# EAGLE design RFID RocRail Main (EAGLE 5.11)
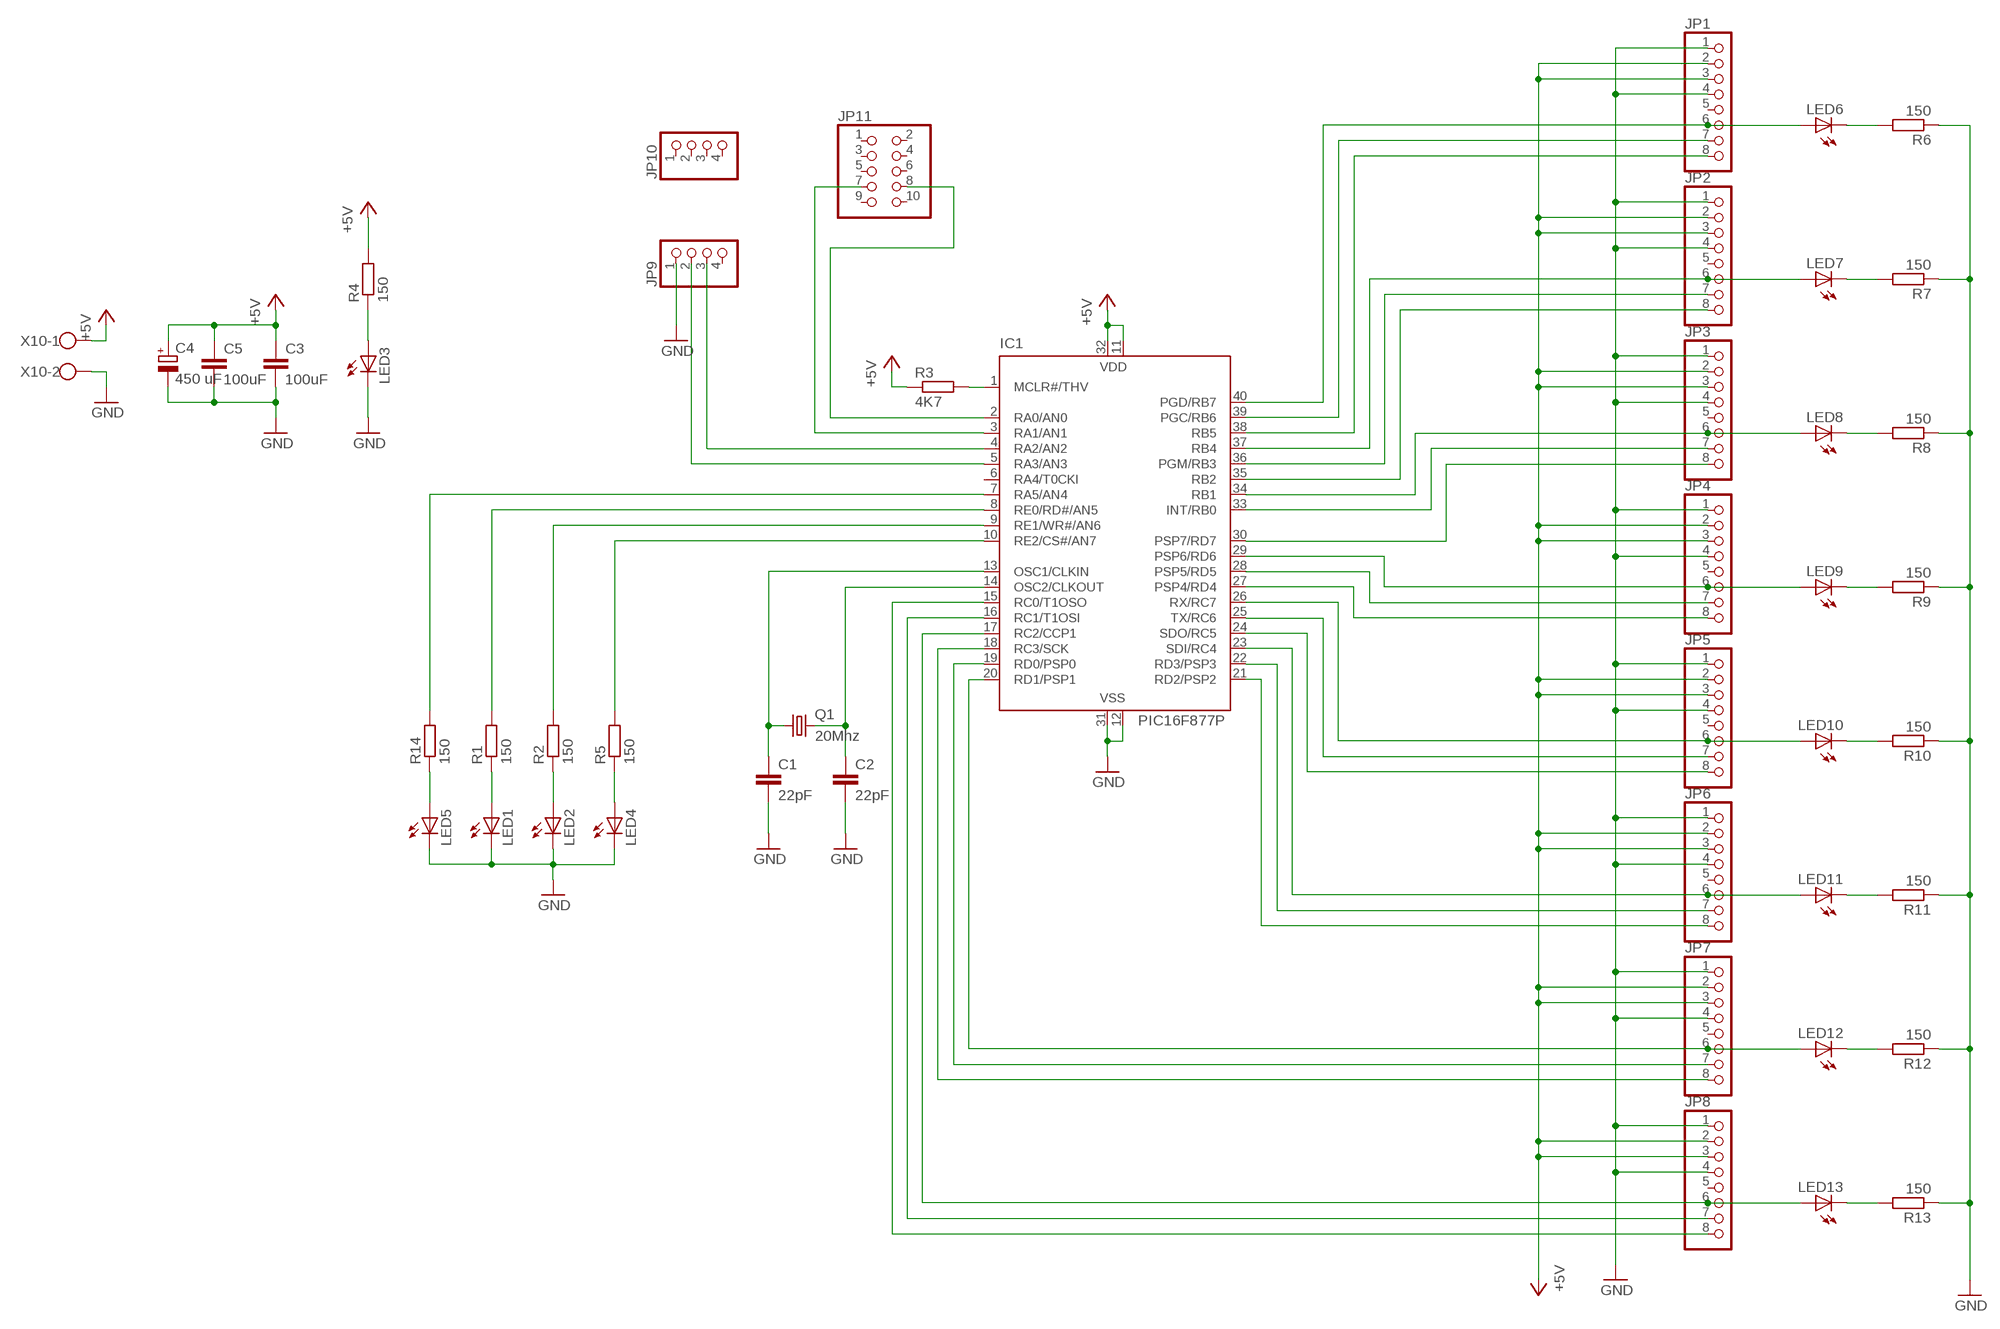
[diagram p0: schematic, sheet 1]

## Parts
C1  22pF  C-EU050-025X075  [C050-025X075]
C2  22pF  C-EU050-025X075  [C050-025X075]
C3  100uF  C-EU050-025X075  [C050-025X075]
C4  450 uF  CPOL-EUE5-13  [E5-13]
C5  100uF  C-EU050-025X075  [C050-025X075]
IC1  PIC16F877P  [DIL40]
JP1  PINHD-1X8  [1X08]
JP2  PINHD-1X8  [1X08]
JP3  PINHD-1X8  [1X08]
JP4  PINHD-1X8  [1X08]
JP5  PINHD-1X8  [1X08]
JP6  PINHD-1X8  [1X08]
JP7  PINHD-1X8  [1X08]
JP8  PINHD-1X8  [1X08]
JP9  PINHD-1X4  [1X04]
JP10  PINHD-1X4  [1X04]
JP11  PINHD-2X5  [2X05]
LED1  LED3MM  [LED3MM]
LED2  LED3MM  [LED3MM]
LED3  LED3MM  [LED3MM]
LED4  LED3MM  [LED3MM]
LED5  LED3MM  [LED3MM]
LED6  LED3MM  [LED3MM]
LED7  LED3MM  [LED3MM]
LED8  LED3MM  [LED3MM]
LED9  LED3MM  [LED3MM]
LED10  LED3MM  [LED3MM]
LED11  LED3MM  [LED3MM]
LED12  LED3MM  [LED3MM]
LED13  LED3MM  [LED3MM]
Q1  20Mhz  CRYSTALHC18U-V  [HC18U-V]
R1  150  R-EU_0207/2V  [0207/2V]
R2  150  R-EU_0207/2V  [0207/2V]
R3  4K7  R-EU_0204/7  [0204/7]
R4  150  R-EU_0204/7  [0204/7]
R5  150  R-EU_0207/2V  [0207/2V]
R6  150  R-EU_0204/7  [0204/7]
R7  150  R-EU_0204/7  [0204/7]
R8  150  R-EU_0204/7  [0204/7]
R9  150  R-EU_0204/7  [0204/7]
R10  150  R-EU_0204/7  [0204/7]
R11  150  R-EU_0204/7  [0204/7]
R12  150  R-EU_0204/7  [0204/7]
R13  150  R-EU_0204/7  [0204/7]
R14  150  R-EU_0207/2V  [0207/2V]
X10  W237-102  [W237-102]

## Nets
+5V: C3.1 C4.+ C5.1 IC1.11(VDD) IC1.32(VDD) JP1.2 JP1.3 JP2.2 JP2.3 JP3.2 JP3.3 JP4.2 JP4.3 JP5.2 JP5.3 JP6.2 JP6.3 JP7.2 JP7.3 JP8.2 JP8.3 R3.1 R4.2 X10.1
GND: C1.2 C2.2 C3.2 C4.- C5.2 IC1.12(VSS) IC1.31(VSS) JP1.1 JP1.4 JP2.1 JP2.4 JP3.1 JP3.4 JP4.1 JP4.4 JP5.1 JP5.4 JP6.1 JP6.4 JP7.1 JP7.4 JP8.1 JP8.4 JP9.1 LED1.K(C) LED2.K(C) LED3.K(C) LED4.K(C) LED5.K(C) R6.1 R7.1 R8.1 R9.1 R10.1 R11.1 R12.1 R13.1 X10.2
N$1: IC1.10(RE2/CS#/AN7) R5.2
N$2: IC1.9(RE1/WR#/AN6) R2.2
N$3: IC1.8(RE0/RD#/AN5) R1.2
N$4: IC1.15(RC0/T1OSO) JP8.8
N$5: IC1.16(RC1/T1OSI) JP8.7
N$6: IC1.17(RC2/CCP1) JP8.6 LED13.A
N$7: IC1.18(RC3/SCK) JP7.8
N$8: IC1.19(RD0/PSP0) JP7.7
N$9: C1.1 IC1.13(OSC1/CLKIN) Q1.1
N$10: IC1.20(RD1/PSP1) JP7.6 LED12.A
N$11: IC1.21(RD2/PSP2) JP6.8
N$12: IC1.22(RD3/PSP3) JP6.7
N$13: IC1.23(SDI/RC4) JP6.6 LED11.A
N$14: IC1.24(SDO/RC5) JP5.8
N$15: IC1.25(TX/RC6) JP5.7
N$16: IC1.26(RX/RC7) JP5.6 LED10.A
N$17: IC1.27(PSP4/RD4) JP4.8
N$18: IC1.28(PSP5/RD5) JP4.7
N$19: IC1.29(PSP6/RD6) JP4.6 LED9.A
N$20: IC1.30(PSP7/RD7) JP3.8
N$21: IC1.33(INT/RB0) JP3.7
N$22: IC1.34(RB1) JP3.6 LED8.A
N$23: IC1.35(RB2) JP2.8
N$24: IC1.36(PGM/RB3) JP2.7
N$25: IC1.37(RB4) JP2.6 LED7.A
N$26: IC1.38(RB5) JP1.8
N$27: IC1.39(PGC/RB6) JP1.7
N$28: IC1.40(PGD/RB7) JP1.6 LED6.A
N$29: IC1.4(RA2/AN2) JP9.3
N$30: C2.1 IC1.14(OSC2/CLKOUT) Q1.2
N$31: IC1.1(MCLR#/THV) R3.2
N$32: IC1.5(RA3/AN3) JP9.2
N$33: IC1.3(RA1/AN1) JP11.7
N$34: LED3.A R4.1
N$35: LED1.A R1.1
N$36: LED2.A R2.1
N$37: IC1.2(RA0/AN0) JP11.8
N$38: IC1.7(RA5/AN4) R14.2
N$39: LED5.A R14.1
N$40: LED6.K(C) R6.2
N$41: LED7.K(C) R7.2
N$42: LED8.K(C) R8.2
N$43: LED9.K(C) R9.2
N$44: LED10.K(C) R10.2
N$45: LED11.K(C) R11.2
N$46: LED12.K(C) R12.2
N$47: LED13.K(C) R13.2
N$72: LED4.A R5.1
Unconnected: IC1.6(RA4/T0CKI) JP1.5 JP2.5 JP3.5 JP4.5 JP5.5 JP6.5 JP7.5 JP8.5 JP9.4 JP10.1 JP10.2 JP10.3 JP10.4 JP11.1 JP11.2 JP11.3 JP11.4 JP11.5 JP11.6 JP11.9 JP11.10

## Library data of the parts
C1-C3 C5 = rcl:C-EU: CAPACITOR, European symbol
C4 = rcl:CPOL-EU: POLARIZED CAPACITOR, European symbol
IC1 = microchip:PIC16F87*: MICROCONTROLLER
JP1-JP8 = pinhead:PINHD-1X8: PIN HEADER
JP9 JP10 = pinhead:PINHD-1X4: PIN HEADER
JP11 = pinhead:PINHD-2X5: PIN HEADER
LED1-LED13 = led:LED: LED
Q1 = crystal:CRYSTAL: CRYSTAL
R1-R14 = rcl:R-EU_: RESISTOR, European symbol
X10 = con-wago-500:W237-102: WAGO SCREW CLAMP

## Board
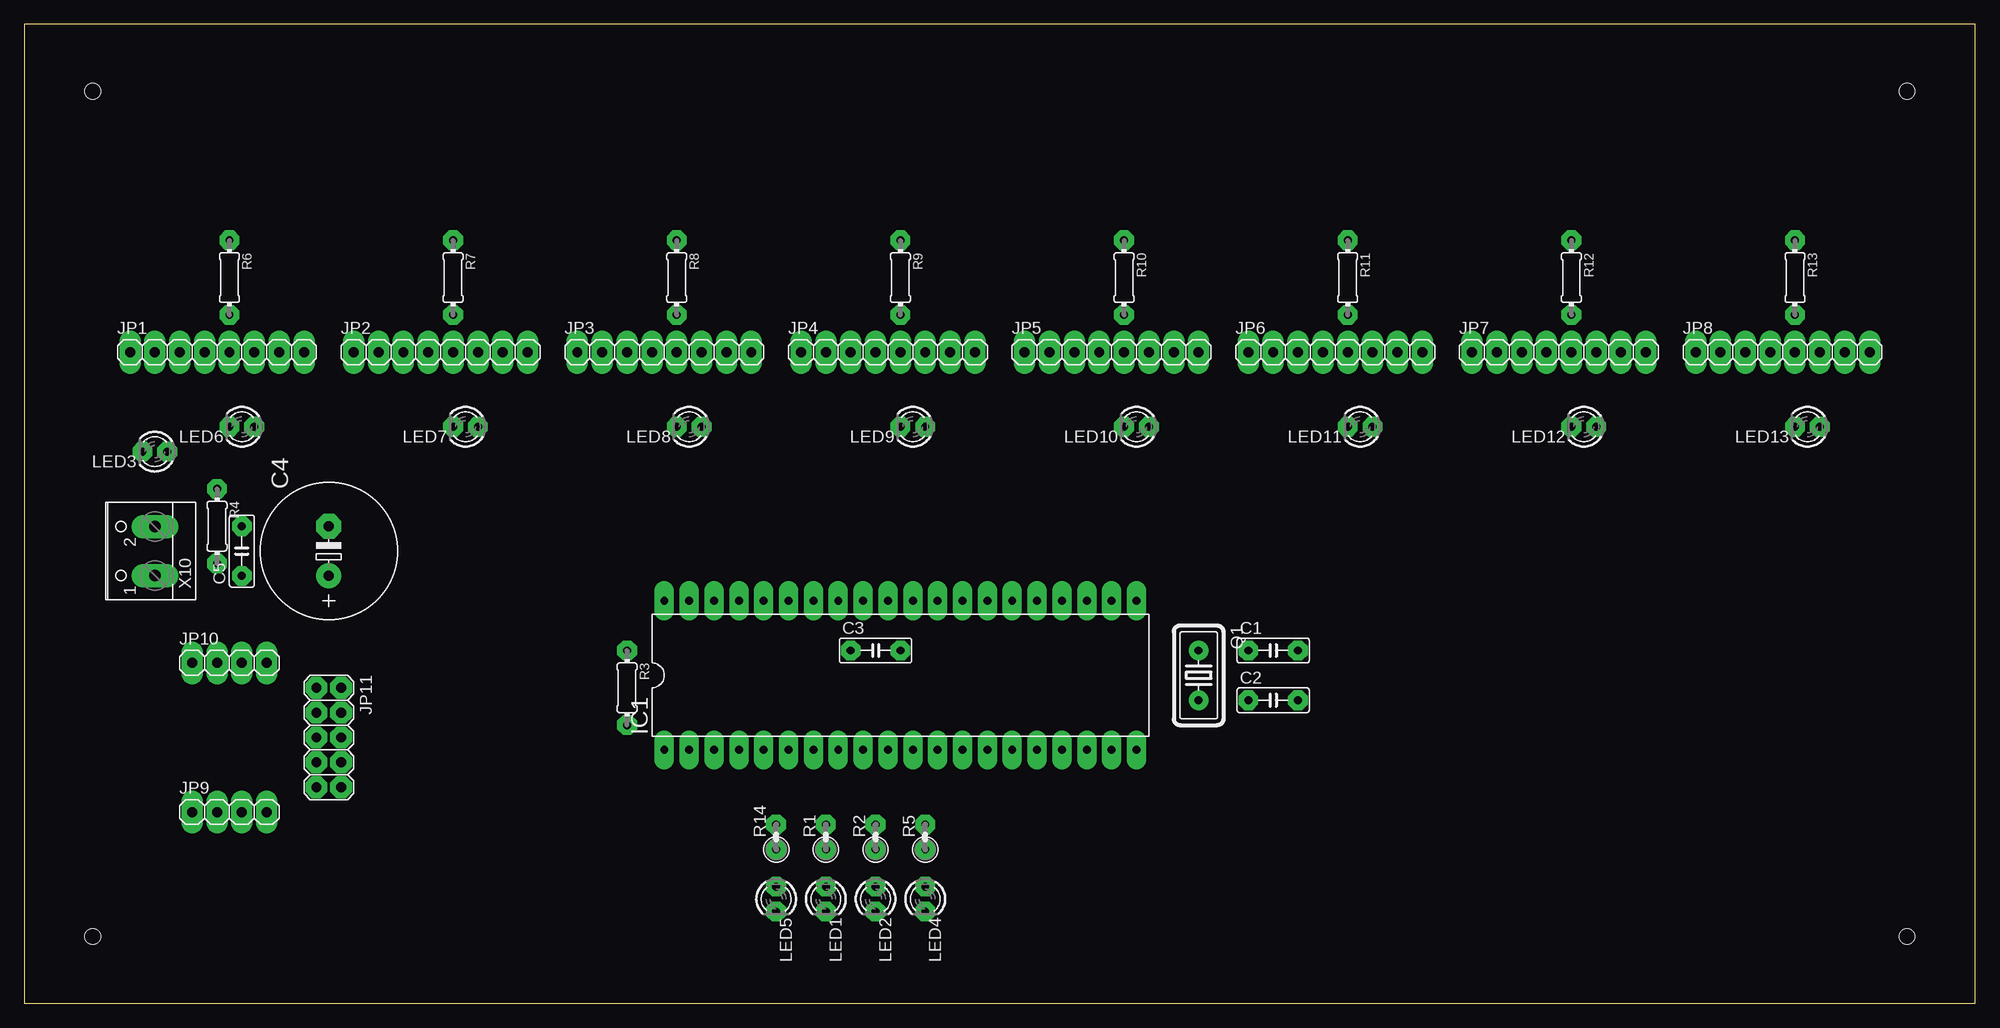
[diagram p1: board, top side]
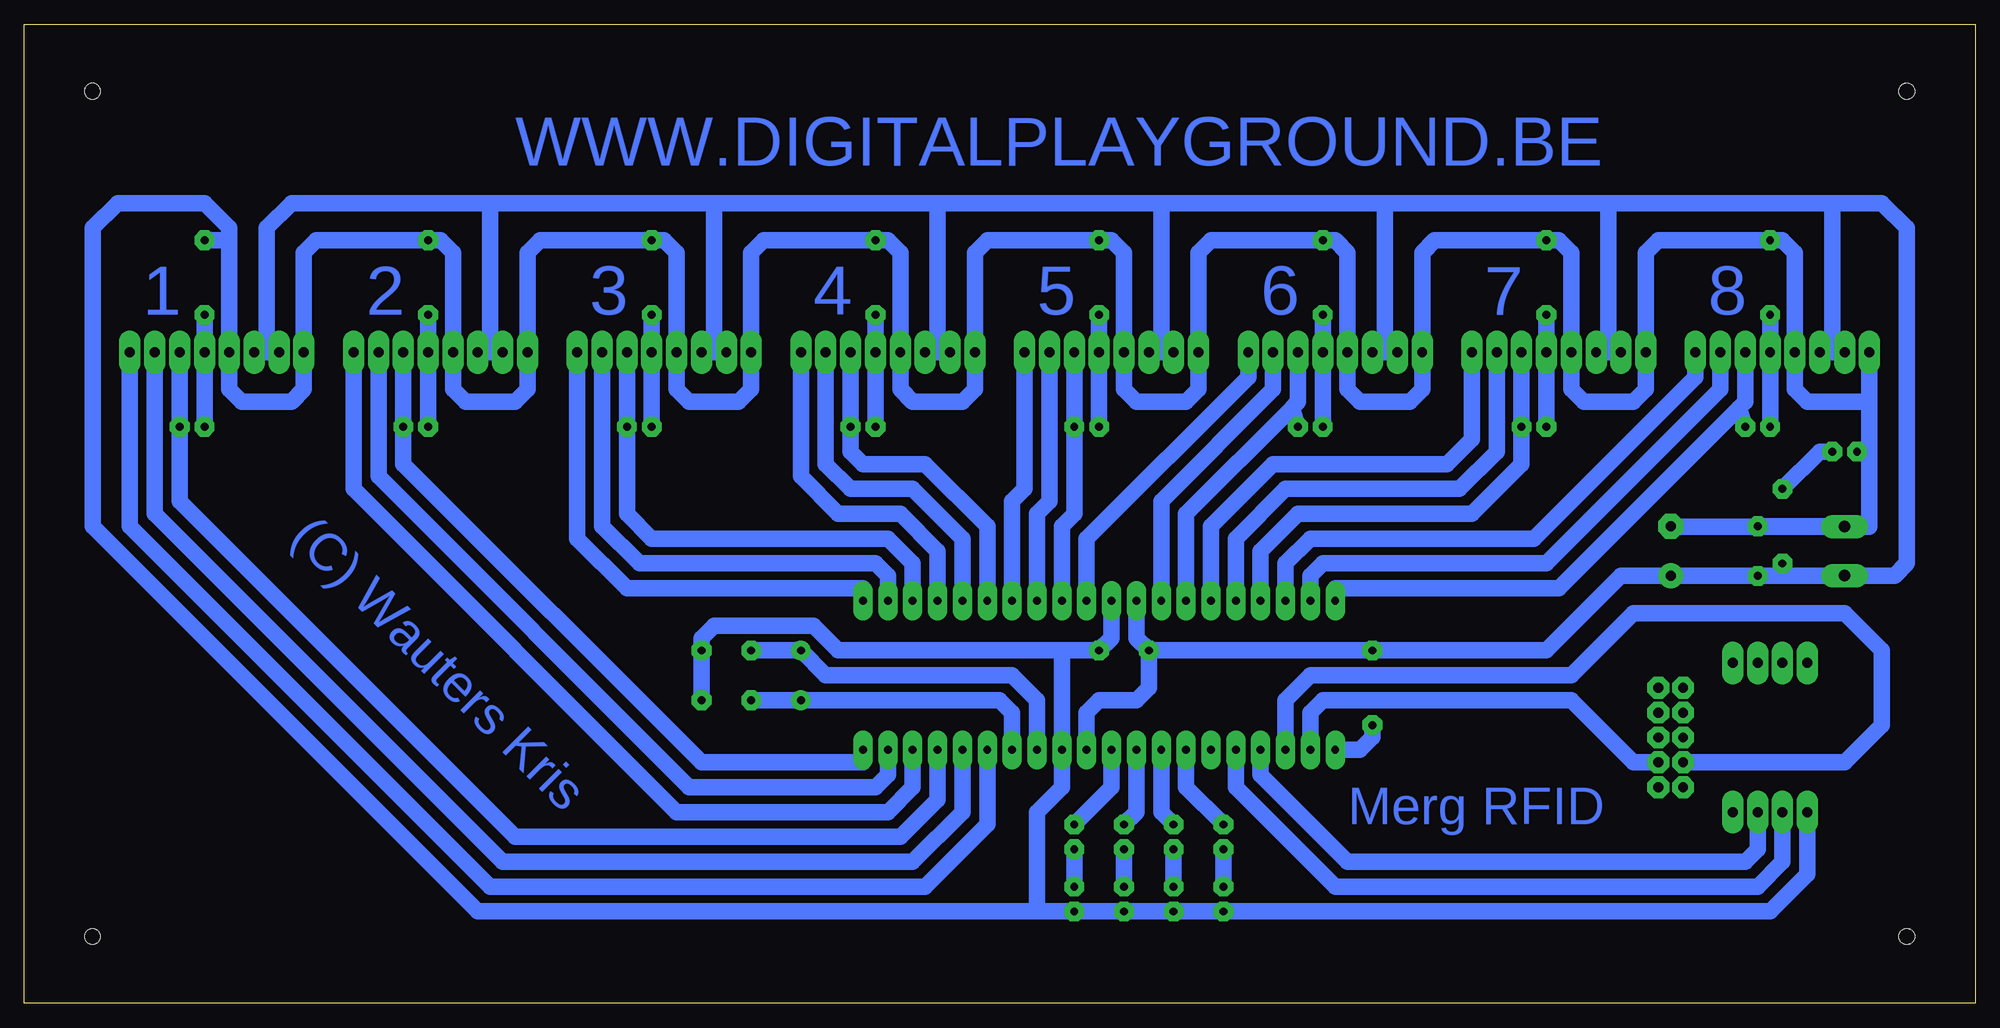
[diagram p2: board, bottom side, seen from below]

Size 199.37 x 100 mm. Coordinates in mm from the lower left corner, seen from the top.
Outline: 0,0 199.37,0 199.37,100 0,100 0,0
Copper layers (1*16): Top 1mm / dielectric 1.5mm / Bottom 1mm
Design rules "DRC settings middle": minimum track width 1.2mm, minimum drill 24mil, track to track 0.4mm, track to pad 0.4mm, pad to pad 0.4mm, via to via 0.4mm, smd to smd 8mil, copper to edge 0.5mm, drill to drill 0.5mm, minimum pad ring 0.6mm, minimum via ring 1mm, stop-mask expansion 4mil, vias tented up to drill 0mil, thermal gap 10mil
Holes 1.6 mm at 6.98,93.18 192.4,93.18 6.98,6.82 192.4,6.82

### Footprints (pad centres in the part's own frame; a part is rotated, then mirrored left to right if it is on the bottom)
C050-025X075 = drill 0.813 octagon: 1 -2.54,0; 2 2.54,0
E5-13 = drill 1.016 pad 2.54 round: + -2.54,0 | drill 1.016 pad 2.54 octagon: - 2.54,0
DIL40 = drill 0.813 long: 1 -24.13,-7.62; 2 -21.59,-7.62; 3 -19.05,-7.62; 4 -16.51,-7.62; 5 -13.97,-7.62; 6 -11.43,-7.62; 7 -8.89,-7.62; 8 -6.35,-7.62; 9 -3.81,-7.62; 10 -1.27,-7.62; 11 1.27,-7.62; 12 3.81,-7.62; 13 6.35,-7.62; 14 8.89,-7.62; 15 11.43,-7.62; 16 13.97,-7.62; 17 16.51,-7.62; 18 19.05,-7.62; 19 21.59,-7.62; 20 24.13,-7.62; 21 24.13,7.62; 22 21.59,7.62; 23 19.05,7.62; 24 16.51,7.62; 25 13.97,7.62; 26 11.43,7.62; 27 8.89,7.62; 28 6.35,7.62; 29 3.81,7.62; 30 1.27,7.62; 31 -1.27,7.62; 32 -3.81,7.62; 33 -6.35,7.62; 34 -8.89,7.62; 35 -11.43,7.62; 36 -13.97,7.62; 37 -16.51,7.62; 38 -19.05,7.62; 39 -21.59,7.62; 40 -24.13,7.62
1X08 = drill 1.016 long: 1 -8.89,0; 2 -6.35,0; 3 -3.81,0; 4 -1.27,0; 5 1.27,0; 6 3.81,0; 7 6.35,0; 8 8.89,0
1X04 = drill 1.016 long: 1 -3.81,0; 2 -1.27,0; 3 1.27,0; 4 3.81,0
2X05 = drill 1.016 octagon: 1 -5.08,-1.27; 2 -5.08,1.27; 3 -2.54,-1.27; 4 -2.54,1.27; 5 0,-1.27; 6 0,1.27; 7 2.54,-1.27; 8 2.54,1.27; 9 5.08,-1.27; 10 5.08,1.27
LED3MM = drill 0.813 octagon: A -1.27,0; K 1.27,0
HC18U-V = drill 0.813 round: 1 -2.54,0; 2 2.54,0
0207/2V = drill 0.813 octagon: 1 -1.27,0; 2 1.27,0
0204/7 = drill 0.813 octagon: 1 -3.81,0; 2 3.81,0
W237-102 = drill 1.194 long: 1 -2.5,-1.27; 2 2.5,-1.27

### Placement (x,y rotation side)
C1  127.63,36.03 0 top
C2  127.63,30.95 0 top
C3  86.99,36.03 0 top
C4  31.11,46.19 90 top
C5  22.22,46.19 90 top
IC1  89.53,33.49 0 top
JP1  19.68,66.51 0 top
JP2  42.54,66.51 0 top
JP3  65.4,66.51 0 top
JP4  88.26,66.51 0 top
JP5  111.12,66.51 0 top
JP6  133.98,66.51 0 top
JP7  156.84,66.51 0 top
JP8  179.7,66.51 0 top
JP9  20.95,19.52 0 top
JP10  20.95,34.76 0 top
JP11  31.11,27.14 270 top
LED1  81.91,10.63 270 top
LED2  86.99,10.63 270 top
LED3  13.33,56.35 180 top
LED4  92.07,10.63 270 top
LED5  76.83,10.63 270 top
LED6  22.22,58.89 180 top
LED7  45.08,58.89 180 top
LED8  67.94,58.89 180 top
LED9  90.8,58.89 180 top
LED10  113.66,58.89 180 top
LED11  136.52,58.89 180 top
LED12  159.38,58.89 180 top
LED13  182.24,58.89 180 top
Q1  120.01,33.49 270 top
R1  81.91,16.98 90 top
R2  86.99,16.98 90 top
R3  61.59,32.22 270 top
R4  19.68,48.73 270 top
R5  92.07,16.98 90 top
R6  20.95,74.13 270 top
R7  43.81,74.13 270 top
R8  66.67,74.13 270 top
R9  89.53,74.13 270 top
R10  112.39,74.13 270 top
R11  135.25,74.13 270 top
R12  158.11,74.13 270 top
R13  180.97,74.13 270 top
R14  76.83,16.98 90 top
X10  12.06,46.19 90 top

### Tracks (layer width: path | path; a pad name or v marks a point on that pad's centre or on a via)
+5V
  Bottom 1.676: 37.46,66.51 JP2.3 | 14.6,81.75 14.6,66.51 JP1.3 JP1.2 | 14.6,81.75 37.46,81.75 | 37.46,81.75 60.32,81.75 | 60.32,81.75 83.18,81.75 | 83.18,81.75 106.04,81.75 | 106.04,81.75 128.9,81.75 | 128.9,81.75 151.76,81.75 | 151.76,81.75 172.08,81.75 174.62,79.21 174.62,66.51 | 151.76,66.51 JP7.2 | 151.76,81.75 151.76,66.51 | 151.76,66.51 JP7.3 | 128.9,66.51 JP6.3 | 128.9,81.75 128.9,66.51 | 128.9,66.51 JP6.2 | 106.04,66.51 JP5.3 | 106.04,66.51 JP5.2 | 106.04,81.75 106.04,66.51 | 83.18,66.51 JP4.2 | 83.18,66.51 JP4.3 | 83.18,81.75 83.18,66.51 | 60.32,66.51 JP3.2 | 60.32,66.51 JP3.3 | 60.32,81.75 60.32,66.51 | 37.46,66.51 JP2.2 | 37.46,81.75 37.46,66.51 | 14.6,81.75 9.52,81.75 6.98,79.21 6.98,44.92 8.21,43.69 X10.1 19.68,43.69 | 174.62,66.51 JP8.3 | 174.62,66.51 JP8.2 | IC1.11 90.8,29.68 89.53,30.95 85.72,30.95 84.45,32.22 C3.1 | IC1.32 85.72,37.3 C3.1 | C3.1 R3.1 43.81,36.03 36.19,43.65 C4.+ C5.1 22.18,43.69 19.68,43.69 | 19.68,43.69 R4.2
GND
  Bottom 1.676: C2.2 C1.2 130.17,37.3 128.9,38.57 118.74,38.57 116.2,36.03 93.34,36.03 | 93.34,36.03 C3.2 88.26,37.3 IC1.31 | X10.2 10.83,48.69 10.79,48.73 10.79,56.35 | 10.79,61.43 10.79,56.35 | 10.79,61.43 JP1.1 | 10.79,61.43 17.14,61.43 18.41,62.7 JP1.4 18.41,76.67 19.68,77.94 R6.1 32.38,77.94 33.65,76.67 JP2.1 33.65,62.7 34.92,61.43 40,61.43 41.27,62.7 JP2.4 41.27,76.67 42.54,77.94 R7.1 55.24,77.94 56.51,76.67 JP3.1 56.51,62.7 57.78,61.43 62.86,61.43 64.13,62.7 JP3.4 64.13,76.67 65.4,77.94 R8.1 78.1,77.94 79.37,76.67 JP4.1 79.37,62.7 80.64,61.43 85.72,61.43 86.99,62.7 JP4.4 86.99,76.67 88.26,77.94 R9.1 100.96,77.94 102.23,76.67 JP5.1 102.23,62.7 103.5,61.43 108.58,61.43 109.85,62.7 JP5.4 109.85,76.67 111.12,77.94 R10.1 123.82,77.94 125.09,76.67 JP6.1 125.09,62.7 126.36,61.43 131.44,61.43 132.71,62.7 JP6.4 132.71,76.67 133.98,77.94 R11.1 146.68,77.94 147.95,76.67 JP7.1 147.95,62.7 149.22,61.43 154.3,61.43 155.57,62.7 JP7.4 155.57,76.67 156.84,77.94 R12.1 169.54,77.94 170.81,76.67 JP8.1 170.81,62.7 172.08,61.43 177.16,61.43 178.43,62.7 JP8.4 178.43,77.94 | X10.2 31.07,48.69 C4.- | C5.2 13.37,48.73 X10.2 | 95.88,9.36 LED4.K LED2.K LED1.K LED5.K 20.95,9.36 17.14,13.17 JP9.1 | 178.43,77.94 178.43,79.21 180.97,81.75 189.86,81.75 192.4,79.21 192.4,48.73 153.03,9.36 95.88,9.36 | 95.88,9.36 95.88,19.52 93.34,22.06 IC1.12 93.34,36.03 | 10.79,56.35 LED3.K | 178.43,77.94 R13.1
N$1
  Bottom 1.676: IC1.10 88.26,22.06 R5.2
N$2
  Bottom 1.676: IC1.9 85.72,19.52 R2.2
N$3
  Bottom 1.676: IC1.8 83.18,19.52 R1.2
N$4
  Bottom 1.676: IC1.15 100.96,18.25 107.31,11.9 151.76,11.9 188.59,48.73 JP8.8
N$5
  Bottom 1.676: IC1.16 103.5,19.52 108.58,14.44 150.49,14.44 186.05,50 JP8.7
N$6
  Bottom 1.676: IC1.17 106.04,20.79 109.85,16.98 149.22,16.98 183.51,51.27 LED13.A JP8.6
N$7
  Bottom 1.676: JP7.8 165.73,52.54 132.71,19.52 111.12,19.52 108.58,22.06 IC1.18
N$8
  Bottom 1.676: IC1.19 111.12,23.33 112.39,22.06 131.44,22.06 163.19,53.81 JP7.7
N$9
  Bottom 1.676: IC1.13 95.88,30.95 98.42,33.49 117.47,33.49 Q1.1 C1.1
N$10
  Bottom 1.676: IC1.20 113.66,24.6 130.17,24.6 160.65,55.08 LED12.A JP7.6
N$11
  Bottom 1.676: IC1.21 113.66,42.38 137.79,42.38 142.87,47.46 JP6.8
N$12
  Bottom 1.676: IC1.22 111.12,43.65 112.39,44.92 136.52,44.92 140.33,48.73 JP6.7
N$13
  Bottom 1.676: IC1.23 108.58,44.92 111.12,47.46 135.25,47.46 137.79,50 LED11.A JP6.6
N$14
  Bottom 1.676: IC1.24 106.04,46.19 109.85,50 116.2,50 120.01,53.81 JP5.8
N$15
  Bottom 1.676: IC1.25 103.5,47.46 108.58,52.54 114.93,52.54 117.47,55.08 JP5.7
N$16
  Bottom 1.676: IC1.26 100.96,48.73 107.31,55.08 113.66,55.08 114.93,56.35 LED10.A JP5.6
N$17
  Bottom 1.676: IC1.27 98.42,51.27 97.15,52.54 JP4.8
N$18
  Bottom 1.676: IC1.28 95.88,50 94.61,51.27 JP4.7
N$19
  Bottom 1.676: IC1.29 93.34,48.73 92.07,50 LED9.A JP4.6
N$20
  Bottom 1.676: JP3.8 74.29,63.97 90.8,47.46 IC1.30
N$21
  Bottom 1.676: JP3.7 71.75,62.7 83.18,51.27 IC1.33
N$22
  Bottom 1.676: IC1.34 80.64,50 69.84,60.8 | 69.84,60.8 69.21,61.43 JP3.6 | 69.84,60.8 LED8.A
N$23
  Bottom 1.676: IC1.35 78.1,48.73 71.75,55.08 53.97,55.08 51.43,57.62 JP2.8
N$24
  Bottom 1.676: IC1.36 75.56,47.46 70.48,52.54 52.7,52.54 48.89,56.35 JP2.7
N$25
  Bottom 1.676: IC1.37 73.02,46.19 69.21,50 51.43,50 46.35,55.08 LED7.A JP2.6
N$26
  Bottom 1.676: IC1.38 70.48,44.92 67.94,47.46 45.08,47.46 28.57,63.97 JP1.8
N$27
  Bottom 1.676: IC1.39 67.94,43.65 66.67,44.92 43.81,44.92 26.03,62.7 JP1.7
N$28
  Bottom 1.676: IC1.40 65.4,42.38 42.54,42.38 24.12,60.8 | 24.12,60.8 23.49,61.43 JP1.6 | LED6.A 24.12,60.8
N$29
  Bottom 1.676: JP9.3 22.22,15.71 23.49,14.44 64.13,14.44 73.02,23.33 IC1.4
N$30
  Bottom 1.676: IC1.14 98.42,29.68 99.69,30.95 Q1.2 C2.1
N$31
  Bottom 1.676: IC1.1 62.86,25.87 61.59,27.14 R3.2
N$32
  Bottom 1.676: JP9.2 19.68,14.44 22.22,11.9 65.4,11.9 75.56,22.06 IC1.5
N$33
  Bottom 1.676: JP11.7 13.33,24.6 9.52,28.41 9.52,36.03 13.33,39.84 34.92,39.84 41.27,33.49 67.94,33.49 70.48,30.95 IC1.3
N$34
  Bottom 1.676: LED3.A 15.87,56.35 R4.1
N$35
  Bottom 1.676: LED1.A R1.1
N$36
  Bottom 1.676: LED2.A R2.1
N$37
  Bottom 1.676: JP11.8 34.92,24.6 41.27,30.95 66.67,30.95 67.94,29.68 IC1.2
N$38
  Bottom 1.676: IC1.7 80.64,22.06 R14.2
N$39
  Bottom 1.676: LED5.A R14.1
N$40
  Bottom 1.676: LED6.K R6.2
N$41
  Bottom 1.676: LED7.K R7.2
N$42
  Bottom 1.676: LED8.K R8.2
N$43
  Bottom 1.676: LED9.K R9.2
N$44
  Bottom 1.676: LED10.K R10.2
N$45
  Bottom 1.676: LED11.K R11.2
N$46
  Bottom 1.676: LED12.K R12.2
N$47
  Bottom 1.676: LED13.K R13.2
N$72
  Bottom 1.676: LED4.A R5.1

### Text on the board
Bottom: WWW.DIGITALPLAYGROUND.BE | 8 | 7 | 6 | 5 | 4 | 3 | 2 | 1 | (C) Wauters Kris | Merg RFID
